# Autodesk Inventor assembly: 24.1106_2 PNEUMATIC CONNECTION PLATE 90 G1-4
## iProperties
Created: 2007-06
Part Number: 24.1106_2 PNEUMATIC CONNECTION PLATE 90 G1-4
Document SubType Name: Assembly
Designer: Andy Moles
Author: Andy Moles
